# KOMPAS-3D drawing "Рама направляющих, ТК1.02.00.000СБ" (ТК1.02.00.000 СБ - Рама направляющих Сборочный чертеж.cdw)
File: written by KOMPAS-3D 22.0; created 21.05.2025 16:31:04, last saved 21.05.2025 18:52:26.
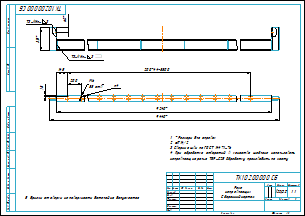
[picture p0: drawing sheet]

Sheet 1: A3, landscape

Document properties: Автор: TC; Масса: 153.815723; Полное имя файла: Рама направляющих.a3d

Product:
- Part/product: Рама направляющих  | designation ТК1.02.00.000СБ
    Масса: 153.815723
    Форматы листов документа: A3
    source file: ТК1.02.00.000 - Рама направляющих.spw
  - Component [assembly]: Двутавр с ребрами  | designation ТК1.02.01.000СБ  | qty 1  | pos. 1  | Масса: 149.626885; Форматы листов документа: A4@4~3; source file: Двутавр с ребрами.a3d, ТК1.02.01.000 - Двутавр с ребрами.spw, ТК1.02.01.000 СБ - Двутавр с ребрами Сборочный чертеж.cdw
  - Component [detail]: Труба$d100х50х4 ГОСТ 8645-68;09Г2 ГОСТ 13663-86$  | designation ТК1.02.00.001  | qty 2  | pos. 2
      Материал: Труба$d80х40х7 ГОСТ 8645-68;09Г2 ГОСТ 13663-86$ (density 7850 kg/m3)
      Масса: 2.076019
      Раздел спецификации: Детали
      Форматы листов документа: б/ч
      Примечание: m=2.07 кг / L=315 мм
      source file: Труба 100х50х4 ГОСТ 8645-68;09Г2 ГОСТ 13663-86$ — копия.m3d
  - Component [standard]: Гайка М12-6H.04.019 ГОСТ 5915-70  | qty 2  | pos. 3  | Масса: 0.0184; Раздел спецификации: Стандартные изделия; Рассекать на разрезах: no
- Component: Обозначение стандартного шва по ГОСТ  | designation ГОСТ 14771-76-Т3-ИНп-@+34~3  | qty 2  | additional columns: 0; 1; 0; 0; 0; ГОСТ 14771-76-Т3-ИНп-@+34~3; ГОСТ 14771-76-Т3-ИНп-@+34~3; 0

Title block, sheet 1: Наименование: Рама / направляющих / Сборочный чертеж; Масса: 153,82; Количество листов документа: 1; Форматы листов документа: A3; stored path: D:\Работа\2025\5. Май\Задание №6 - Тележка для крыши\3Д\Рама направляющих\ТК1.02.00.000 СБ - Рама направляющих Сборочный чертеж.cdw

Views: Проекционный вид 8, Местный разрез 1, Местный разрез 2
Referenced files in D:\Работа\2025\5. Май\Задание №6 - Тележка для крыши\3Д\Рама направляющих\: Труба 100х50х4 ГОСТ 8645-68;09Г2 ГОСТ 13663-86$ — копия.m3d, Рама направляющих.a3d, Двутавр с ребрами.a3d, Ребро жесткости.m3d
Referenced files in D:\Рабочая папка\АРХИВ\612\05\Задание №6 - Тележка для крыши\3Д\Рама направляющих\: Рама направляющих.a3d
Referenced files in D:\Program Files\ASCON\KOMPAS-3D v22\Libs\PolynomLib\DATA\vault\Methods\Kompas\3D\: PLib_IBeams_GOST_8239_1501.m3d, PLib_Nut_OST92_900.m3d
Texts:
  Т3-ИНп- 3
  ТК1.02.00.000
  Двутавр $d 16 ГОСТ 8239-89 ; Ст3сп ГОСТ 535-2005$
  Двутавр  16 ГОСТ 8239-89 / Ст3сп ГОСТ 535-2005
  Ребро жесткости
  ТК1.02.01.001
  ТК1.02.01.001 Ребро жесткости
  Двутавр с ребрами
  ТК1.02.01.000
  ТК1.02.01.000 Двутавр с ребрами
  Труба$d100х50х4 ГОСТ 8645-68;09Г2 ГОСТ 13663-86$
  ТК1.02.00.001
  ТК1.02.00.001 Труба100х50х4 ГОСТ 8645-68/09Г2 ГОСТ 13663-86
  Гайка М12-6H.04.019 ГОСТ 5915-70
  Рама направляющих
  ТК1.02.00.000
  ТК1.02.00.000 СБ Рама направляющих
Dimensions and other numbers on the sheet: 315; 60; 9; 1:1; 1; 153,82

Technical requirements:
  *Размеры для справок.
  ±IT14/2.
  Сварные швы по ГОСТ 14471-76.
  При обработке отверстий в качестве шаблона использовать
  направляющие рельс TBR-C25. Обработку производить по месту.
  Брызги от сварки на поверхности деталей не допускаются.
